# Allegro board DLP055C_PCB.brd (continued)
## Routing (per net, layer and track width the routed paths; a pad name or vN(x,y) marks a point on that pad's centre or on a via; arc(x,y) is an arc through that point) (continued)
HDMI_CEC: length 295.4
  TOP w0.191: v1(118.66,141.92) 118.66,142.57 118.66,142.57 118.66,142.66 118.66,142.66 118.66,143.08 118.66,143.08 J3.23 ; v1(156.41,67.09) 156.13,67.37 156.13,67.76 R234.1 ; J42.49 154.38,8.87 154.38,8.87 154.38,9.29 154.38,9.29 154.38,10.65 156.1,12.37 156.1,14.33 156.1,14.34 TP47.1
  LY12 w0.122: v1(175.74,42.02) 178.18,44.46 179.9,44.46 183.8,48.35 183.8,127.11 181.23,129.68 181.23,144.43 179.12,146.54 161.21,146.54 159,144.33 148.84,144.33 145.39,147.79 134.11,147.79 130.27,143.95 119.45,143.95 118.66,143.16 v1(118.66,141.92)
  BOTTOM w0.191: TP47.1 155.26,16.1 155.26,18.81 154.81,19.26 154.81,40.67 156.74,42.6 169.52,42.6 170.94,41.18 174.9,41.18 v1(175.74,42.02) 175.74,42.38 175.03,43.09 171.6,43.09 170.66,44.03 170.66,46.14 169.74,47.05 167.97,47.05 167.55,47.47 164.65,47.47 162.07,50.05 162.07,50.94 163.02,51.89 163.02,52.25 163,52.28 163,52.98 163.02,53 163.02,55.75 162.81,55.97 162.81,56.59 162.78,56.61 162.78,57.58 162.59,57.77 157.48,57.77 156.53,58.72 149.44,58.72 146.94,61.22 146.94,63.89 147.62,64.58 155.55,64.58 156.41,65.44 v1(156.41,67.09)
HEARTBEAT: length 39.6
  TOP w0.191: U12.2 v1(177.8,88.87) ; U15.AA3 v1(157.45,75.9)
  LY3 w0.076: 158.96,76.49 158.03,76.49 v1(157.45,75.9)
  LY3 w0.102: 158.96,76.49 159.06,76.38 166.91,76.38 166.99,76.3
  LY3 w0.122: 166.99,76.3 174.87,76.3 v1(177.01,78.44)
  LY12 w0.122: v1(177.01,78.44) 177.01,81.51 176.85,81.67 176.85,86.03 177.8,86.98 v1(177.8,88.87)
  BOTTOM w0.191: v1(157.45,75.9) 157.45,72.97 157.68,72.73 157.68,72.42 157.71,72.39 157.71,71.69 157.68,71.67 157.68,71 157.59,70.91 R237.2
HEARTBEAT_DRVR: length 2.6
  TOP w0.191: R32.2 179.71,91.12 179.18,91.65 178.49,91.65 U12.4
HEARTBEAT_LED: length 1.3
  TOP w0.191: R32.1 D15.1
HOLD_BOOTZ: length 19.9
  TOP w0.191: U15.AE4 v1(161.45,76.9)
  LY3 w0.122: v1(170.5,77.29) 166.99,77.29 166.89,77.39 161.94,77.39 v1(161.45,76.9)
  BOTTOM w0.191: v1(170.5,77.29) 170.93,77.72 R119.1 170.93,85.53 170.81,85.65 J9.1
HTPDN: length 75.9
  TOP w0.191: v1(117.67,141) 117.66,141 117.66,142.66 117.66,142.66 117.66,143.08 117.66,143.08 J3.25 ; U15.E17 v1(140.45,90.9)
  LY3 w0.122: v1(140.45,90.9) 139.23,92.11 124.31,92.11 124.14,91.95 v1(121.96,91.95) ; v1(117.67,141) 118.4,141 TP5.1
  LY12 w0.122: TP5.1 121.1,138.29 121.1,132.37 121.41,132.06 121.41,120.68 122.66,119.44 122.66,109.9 122.7,109.85 122.7,109.47 122.66,109.42 122.66,109.33 120.65,107.33 120.65,94.7 121.96,93.39 v1(121.96,91.95)
ICE_RSTZ: length 15.4
  TOP w0.191: U39.2 v1(77.79,11.45)
  LY12 w0.122: v1(77.79,11.45) 77.79,11.96 82.87,17.04 J501.15
  BOTTOM w0.191: R504.1 J501.15
ICTSEN: length 4
  TOP w0.191: U15.K26 v1(145.45,99.9)
  BOTTOM w0.191: R113.2 144.93,102.41 144.93,100.42 v1(145.45,99.9)
IIC0_SCL: length 402.3
  TOP w0.191: v1(33.63,84.87) 33.93,84.57 U561.5 ; J53.1 14.41,107.2 17.47,107.2 17.88,106.79 17.88,104.39 17.58,104.09 U559.5 ; v1(121.15,142.11) 121.16,142.13 121.16,142.66 121.16,142.66 121.16,143.08 121.16,143.08 J3.18 ; U15.E27 v1(140.45,100.9) ; J16.1 v1(110.2,34.87)
  LY3 w0.122: v1(122.47,99.64) 133.42,99.64 134.13,100.35 138.59,100.35 138.7,100.46 140,100.46 v1(140.45,100.9) ; J53.1 14.3,107.32 16.86,107.32 20.57,103.62 20.57,81.77 21.18,81.16 26.31,81.16 27.73,82.58 32.13,82.58 32.51,82.97 32.51,84.46 32.91,84.87 v1(33.63,84.87) ; v1(46.27,145.04) 46.3,145.07 62.62,145.07 63.26,144.43 71.33,144.43 72.22,145.32 77.12,145.32 79.61,142.83 86.18,142.83 90.47,147.13 100.64,147.13 103.57,144.2 120.44,144.2 121.15,143.5 v1(121.15,142.11)
  LY12 w0.122: v1(46.27,145.04) 48.23,143.09 48.23,122.22 46.12,120.12 46.12,96.21 43.77,93.86 41.15,93.86 38.6,91.31 38.6,86.09 38.25,85.73 35.71,85.73 34.84,84.87 v1(33.63,84.87) ; v1(121.15,142.11) 121.59,141.67 121.59,136.85 122.66,135.78 122.66,123.67 121.69,122.7 121.69,121.09 122.94,119.84 122.94,110 122.97,109.97 122.97,109.35 122.94,109.32 122.94,101.66 122.47,101.19 v1(122.47,99.64) 122.47,82.59 123.72,81.34 123.72,73.59 124.46,72.86 124.46,71.31 123.08,69.94 121.33,69.94 119.73,68.33 119.48,68.33 117.37,70.44 110.03,70.44 108.83,69.24 108.83,58.91 104.54,54.62 104.54,46.9 103.3,45.65 103.3,41.67 110.1,34.87 v1(110.2,34.87) 110.2,34.76 117.52,27.44 117.52,18.65 119.99,16.19 119.99,8.95 121.99,6.94 v1(121.99,4.2)
  BOTTOM w0.191: J53.1 16.08,107.31 R585.2 ; v1(121.99,4.2) 121.36,4.2 121.08,3.92 U36.1 ; R147.1 110.2,33.89 v1(110.2,34.87)
IIC0_SDA: length 391.2
  TOP w0.191: U559.4 v1(18.85,99.49) 19.1,99.25 34.97,99.25 35.91,98.31 35.91,94.12 36.39,93.63 v1(36.39,85.18) 37,84.57 U561.4 ; U15.D29 v1(139.45,102.9) ; J3.20 120.16,143.08 120.16,143.08 120.16,142.66 120.16,142.66 v1(120.16,142.19) ; J16.2 v1(111.45,35.26)
  LY3 w0.122: v1(139.45,102.9) 138.93,102.39 138.21,102.39 137.22,103.38 137.14,103.38 136.93,103.59 136.93,104.61 135.23,106.31 130.78,106.31 129.03,108.06 128.45,108.06 126.83,109.68 122.25,109.68 v1(122.23,109.66) ; v1(47.6,144.48) 62.38,144.48 63.01,143.85 71.57,143.85 72.46,144.74 76.88,144.74 79.17,142.45 86.91,142.45 91,146.54 100.4,146.54 103.32,143.62 119.63,143.62 120.16,143.09 v1(120.16,142.19)
  LY12 w0.122: v1(122.23,109.66) 120.16,111.73 120.16,137.7 119.73,138.13 119.73,139.38 120.75,140.4 120.75,141.59 v1(120.16,142.19) ; v1(139.45,102.9) 137.93,101.38 135.53,101.38 131.92,97.77 131.92,91.04 131.29,90.41 129.74,90.41 127.3,87.97 127.3,85.45 131.03,81.72 131.03,75.55 131.9,74.68 131.9,72.2 130.91,71.21 127.78,71.21 127.33,70.75 127.33,68.06 126.54,67.27 119.99,67.27 118.94,68.31 112.62,68.31 110.64,66.33 110.64,58.96 110.31,58.63 110.31,55.48 113.31,52.49 113.31,35.65 112.99,35.33 111.53,35.33 v1(111.45,35.26) 118.23,28.47 118.23,18.83 120.47,16.6 120.47,9.61 v1(121.97,8.11) ; v1(36.39,85.18) 38.6,85.18 39.01,85.58 39.01,91.14 41.32,93.46 43.94,93.46 46.53,96.05 46.53,119.95 48.64,122.06 48.64,143.44 v1(47.6,144.48)
  BOTTOM w0.191: v1(18.85,99.49) 18.85,103.48 17.83,104.5 13.92,104.5 J54.1 9.32,107.31 R599.2 ; v1(111.45,35.26) 111.45,34.76 111.44,34.75 R146.1 ; U36.8 121.08,6.86 121.08,6.86 121.08,7.23 v1(121.97,8.11)
IIC1_SCL: length 277.1
  TOP w0.191: U15.T2 v1(152.45,74.9) ; v1(134.89,23.4) 134.93,23.36 J21.4 ; v1(123.15,142.09) 123.16,142.09 123.16,142.62 123.16,142.63 123.16,143.04 123.16,143.04 J3.14 ; U30.6 v1(106.36,54.27) ; J12.1 v1(110.2,41.84)
  LY3 w0.076: 136.04,74.49 145.7,74.49 145.87,74.31 146.73,74.31 147.08,73.97 147.73,73.97
  LY3 w0.102: v1(152.45,74.9) 152.05,74.5 151.08,74.5 149.92,73.34 ; 148.35,73.34 147.73,73.97 ; 136.04,74.49 135.88,74.32
  LY3 w0.122: 148.35,73.34 148.38,73.31 149.89,73.31 149.92,73.34 ; v1(144.37,54.72) 142.82,54.72 142.66,54.56 142.66,53.18 138.11,48.64 138.11,48.37 137.37,47.62 137.3,47.62 137.15,47.48 115.03,47.48 113.71,48.8 113.71,51.34 111.58,53.48 107.15,53.48 v1(106.36,54.27) ; 135.88,74.32 135.46,73.9 130.96,73.9 v1(130.54,74.32) ; v1(112.66,36.42) 122.55,36.42 124.35,34.62 127.71,34.62 127.93,34.4 133.73,34.4 135.45,32.67 136.7,32.67 141.14,28.23 141.14,27.29 137.89,24.04 135.14,24.04 134.93,23.82 134.93,23.44 v1(134.89,23.4)
  LY12 w0.122: v1(124.86,1.41) 124.86,3.79 129.28,8.21 130.02,8.21 132.53,10.73 132.53,15.33 134.93,17.72 134.93,23.36 v1(134.89,23.4) ; v1(152.45,74.9) 152.95,74.39 152.95,73.39 153.11,73.24 153.11,68.79 154.22,67.67 154.22,65.03 153.16,63.97 152.26,63.97 151.84,63.55 151.84,62.04 150.16,60.36 148.32,60.36 148.32,60.36 148.16,60.36 146.41,58.61 146.41,58.47 146.38,58.44 146.38,58.4 146.38,58.4 146.38,57.62 146.22,57.47 146.22,57.24 146.22,56.02 144.93,54.72 v1(144.37,54.72) ; v1(106.36,54.27) 106.36,53.68 106.39,53.65 106.39,51.27 105.85,50.73 105.85,39.67 109.77,35.76 112.53,35.76 112.66,35.89 v1(112.66,36.42) 112.66,40.84 112.01,41.49 112.01,42.05 111.6,42.45 110.81,42.45 v1(110.2,41.84) ; v1(130.54,74.32) 130.11,74.75 130.11,78.54 123.84,84.81 123.84,141.4 v1(123.15,142.09)
  BOTTOM w0.191: R140.1 110.2,40.87 v1(110.2,41.84) ; v1(124.86,1.41) 124.86,1.81 124.61,2.07 124.33,2.07 124.2,2.19 124.2,2.92 U37.1
IIC1_SDA: length 260.4
  TOP w0.191: U30.5 v1(107.63,54.26) ; U15.T5 v1(152.45,77.9) ; J21.3 v1(133.68,23.42) ; J12.2 v1(111.45,41.84) ; J3.16 122.16,143.04 122.16,143.04 122.16,142.63 122.16,142.62 122.16,142.09 v1(122.16,142.09)
  LY3 w0.076: 135.88,77.51 135.9,77.49 149.98,77.49 150.04,77.43
  LY3 w0.102: 150.04,77.43 150.69,77.43 150.96,77.7 150.96,78.18 151.2,78.42 151.94,78.42 152.45,77.91 v1(152.45,77.9)
  LY3 w0.122: v1(144.83,55.89) 143.15,55.89 142.22,54.96 142.22,53.36 137.85,48.98 137.85,48.48 137.26,47.89 136.75,47.89 136.62,47.76 115.36,47.76 114.14,48.98 114.14,51.52 111.4,54.26 v1(107.63,54.26) ; 135.88,77.51 135.28,77.51 135.21,77.43 134.48,77.43 134.21,77.71 134.21,77.81 133.85,78.17 130.06,78.17 128.32,79.91 v1(126.07,79.91) ; v1(133.68,23.42) 133.68,24.34 134.59,25.26 138.3,25.26 139.34,26.3 139.34,28.38 133.91,33.81 122.16,33.81 120.54,32.19 117.77,32.19 114.22,35.74 112.2,35.74 v1(111.58,36.36)
  LY12 w0.122: v1(152.45,77.9) 152.46,77.9 152.95,77.4 152.95,75.75 152.7,75.5 151.76,75.5 151.02,74.76 151.02,73.19 150.44,72.6 150.44,68.55 151.74,67.26 151.74,66.51 151.69,66.47 151.69,65.61 151.74,65.57 151.74,64.97 150.83,64.06 150.83,62.91 150.52,62.6 150.52,62.57 149.2,61.25 149.17,61.25 148.83,60.92 147.93,60.92 145.85,58.84 145.85,58.7 145.82,58.67 145.82,58.64 145.82,58.63 145.82,57.87 145.54,57.59 145.54,56.6 v1(144.83,55.89) ; 111.45,41.75 110.53,40.83 109.75,40.83 108.43,42.15 108.43,53.46 v1(107.63,54.26) ; 111.45,41.75 111.45,40.19 112.14,39.51 112.14,36.92 v1(111.58,36.36) ; 111.45,41.75 v1(111.45,41.84) ; v1(124.26,11.76) 124.86,11.76 125.98,12.89 125.98,16.09 127.1,17.2 127.46,17.2 v1(133.68,23.42) ; v1(126.07,79.91) 123.25,82.73 123.25,135.94 121.94,137.25 121.94,139.02 122.16,139.24 v1(122.16,142.09)
  BOTTOM w0.191: U37.8 124.26,6.9 124.26,6.9 124.26,7.32 124.26,7.32 v1(124.26,11.76) ; v1(111.45,41.84) 111.45,40.85 R139.1
IIC2_SCL: length 78.3
  TOP w0.191: v1(175.15,45.96) 174.7,45.52 U34.8 173.88,46.35 R79.1 ; J536.1 v1(165.45,37.78) ; J17.7 v1(184.86,38.35)
  LY3 w0.122: v1(175.15,45.96) 174.31,45.12 174.31,40.72 173.15,39.56 167.22,39.56 v1(165.45,37.78)
  BOTTOM w0.191: R124.1 155.64,71.94 155.64,70.94 155.11,70.41 155.11,69.5 157.07,67.54 157.07,65.47 155.93,64.33 155.93,61.54 157.15,60.32 157.15,60.04 157.42,59.77 157.84,59.77 158.42,59.18 162.62,59.18 164.46,57.34 164.46,51.38 164.11,51.02 164.11,49.51 165.01,48.6 171.24,48.6 173.23,46.61 174.5,46.61 v1(175.15,45.96) 176.8,45.96 177.95,44.81 177.95,43.7 181.91,39.73 183.1,39.73 R142.1 184.49,38.35 v1(184.86,38.35) ; R885.1 165.45,36.75 v1(165.45,37.78)
IIC2_SDA: length 76.9
  TOP w0.191: v1(169.71,45.91) 170.1,45.52 U34.1 170.93,46.35 R78.1 170.63,46.69 170.63,47.61 171.1,48.08 176.21,48.08 180.02,44.26 180.02,40.98 v1(183.16,37.85) J17.6 ; J536.2 166.69,36.2 v1(166.69,37.79)
  LY3 w0.122: v1(168.44,71.81) 166.94,73.31 158.13,73.31 v1(156.87,72.04)
  LY12 w0.122: v1(168.44,71.81) 169.85,70.4 169.85,68.72 169.13,68 169.13,51.64 169.71,51.05 v1(169.71,45.91) 169.08,45.28 169.08,44.41 166.7,42.02 166.7,37.8 v1(166.69,37.79)
  BOTTOM w0.191: v1(183.16,37.85) 183.81,37.85 R143.1 ; R127.1 156.53,72.38 v1(156.87,72.04) ; R884.1 v1(166.69,37.79)
IIC_BUSY: length 403.8
  TOP w0.191: TP46.1 8.17,112 12.37,112 13.18,112.81 13.18,114.84 13.86,115.53 15.39,115.53 16.11,114.8 ; 16.11,114.8 v1(16.11,114.78) ; 16.11,114.8 16.46,114.45 U26.34 ; TP6.1 121.66,139.96 J3.17 ; U562.10 21.89,79.35 21.38,79.87 21.38,81.39 22.53,82.53 22.53,84.44 TP146.1 ; J42.51 155.38,10.02 156.73,11.38 v1(158.33,11.38) ; U15.V1 v1(153.95,72.98)
  LY3 w0.122: v1(16.11,114.78) 17.01,113.88 17.22,113.88 18.94,112.15 18.94,108.54 23.26,104.23 23.26,94.19 22.5,93.43 22.5,90.53 23.5,89.53 46.36,89.53 55.24,80.65 101.44,80.65 103.56,82.77 104.91,82.77 105.34,82.34 105.34,81.49 105.94,80.89 108.01,80.89 108.12,80.77 108.12,74.28 109.35,73.05 113.13,73.05 113.18,73 114.78,73 114.83,73.05 114.92,73.05 116.07,74.19 121.24,74.19 122.2,73.24 126.66,73.24 126.8,73.09 v1(130.7,73.09) 130.75,73.05 135.84,73.05 136.04,73.25 137.51,73.25 137.6,73.34 146.04,73.34 146.18,73.2 146.48,73.2 147.77,71.9 148.99,71.9 149.78,72.69 150.05,72.69 150.71,73.35 153.58,73.35 v1(153.95,72.98)
  LY12 w0.122: TP6.1 123.53,138.09 123.53,84.45 129.63,78.36 129.63,74.17 v1(130.7,73.09) ; v1(153.95,72.98) 153.95,70.34 156.91,67.38 156.91,65.91 156.76,65.76 156.76,65.71 156.59,65.54 156.59,65.53 156.57,65.51 156.57,65.5 155.8,64.73 155.79,64.73 153.85,62.79 153.85,62.4 153.19,61.73 153.15,61.73 152.53,61.12 151.71,61.12 150.39,59.8 149.94,59.8 148.39,59.8 146.96,58.37 146.96,58.23 146.94,58.21 146.94,58.17 146.94,58.17 146.94,56.13 146.94,56.13 146.94,56.09 147.13,55.9 147.13,54.96 146.61,54.43 145.64,54.43 144.09,52.88 144.09,52.25 143.58,51.74 143.58,51.64 143.56,51.62 143.56,49.99 143.58,49.97 143.58,49.9 144.71,48.77 148.21,48.77 148.74,48.24 151.94,48.24 155.22,44.97 155.22,34.76 155.72,34.26 155.72,28.72 155.04,28.04 155.04,18.09 158.33,14.8 v1(158.33,11.38) ; TP46.1 4.87,108.7 4.87,92.19 6.22,90.84 20.14,90.84 22.54,88.44 TP146.1
  BOTTOM w0.191: v1(153.95,72.98) 153.96,72.97 R128.1
IIC_SCL_FP: length 25.9
  TOP w0.203: v1(134.88,9.64) 134.88,9.28 134.94,9.21 134.94,8.79 134.88,8.72 J42.10
  LY12 w0.122: v1(134.88,9.64) 134.9,9.62 134.9,9.2 134.9,9.2 134.9,8.81 134.9,8.8 134.9,8.39 127.22,0.72 122.81,0.72 122.47,1.06 v1(122.47,1.73)
  BOTTOM w0.191: U36.4 119.58,2.06 119.58,2.06 119.58,1.65 119.58,1.64 119.58,1.45 119.9,1.13 121.87,1.13 v1(122.47,1.73) 122.76,2.02 U37.4
IIC_SDA_FP: length 22.1
  TOP w0.185: J42.8 v1(133.88,10.38)
  LY3 w0.122: v1(119.23,7.41) 119.3,7.41 119.54,7.65 121.41,7.65 121.74,7.33 v1(122.39,7.33) 123.71,8.64 130.78,8.64 132.51,10.37 133.86,10.37 v1(133.88,10.38)
  BOTTOM w0.191: v1(119.23,7.41) 119.58,7.06 U36.5 ; U37.5 122.77,5.93 122.77,6.95 v1(122.39,7.33)
IR0: length 7.8
  TOP w0.191: U53.1 114.27,81.57 114.27,80.98 112.71,79.43 J88.1
IR0_PWR: length 6.3
  BOTTOM w0.191: C697.2 110.1,88.27 110.55,87.81 111.38,87.81 R257.1 111.44,86.36 U53.3
IR1: length 8.9
  LY12 w0.122: U54.1 106.5,83.32 104.29,83.32 103.82,82.85 J90.1
IR1_PWR: length 6.3
  BOTTOM w0.191: U54.3 103.19,87.74 R258.1 102.55,88.38 C698.2
J9_SP1: length 4.6
  TOP w0.191: TP56.1 87.24,8.97 87.72,8.97 88.15,8.54 J44.1
J9_SP2: length 3.2
  TOP w0.191: J44.2 88.65,9.25 88.65,9.25 88.65,9.66 88.65,9.66 88.65,10.73 TP55.1
J9_SP9: length 3.3
  TOP w0.185: TP54.1 92.15,10.55 J44.9
J9_SP46: length 4.3
  TOP w0.191: TP50.1 111.72,9.8 111.3,9.8 110.65,9.16 110.65,9.07 110.65,9.07 110.65,8.66 110.65,8.65 J44.46
J9_SP49: length 5
  TOP w0.191: TP49.1 114.62,9.83 113.89,9.1 112.5,9.1 112.15,8.76 J44.49
J9_SP50: length 6.4
  TOP w0.191: J44.50 112.65,8.52 112.87,8.74 114.01,8.74 114.64,9.37 115.74,9.37 TP48.1
J10_SP13: length 7.7
  TOP w0.191: TP40.1 81.6,10.82 82.83,12.05 86.03,12.05 J43.13
KEYPD_11: length 5.2
  TOP w0.191: R857.2 9.65,121.28 9.65,120.46 9.37,120.18 J69.11
KEYPD_12: length 6.3
  TOP w0.191: R858.2 9.63,123.2 8.94,123.2 8.68,122.94 8.68,121.24 8.12,120.68 J69.12
KEYPD_13: length 7.4
  TOP w0.191: R152.2 9.62,125.08 8.61,125.08 7.84,124.32 7.84,121.75 7.27,121.18 J69.13
KEYPD_DOWN: length 27.2
  TOP w0.191: J69.4 7.43,116.68 v1(8.54,115.57) R597.1 ; U26.23 v1(20.56,119.95)
  LY3 w0.122: v1(8.54,115.57) 7.17,115.57 5.97,116.77 5.97,120.05 6.35,120.43 13.86,120.43 14.28,120.01 20.51,120.01 v1(20.56,119.95)
KEYPD_LED_HOT: length 15.1
  TOP w0.191: v1(12.4,121.38) 12.3,121.28 R857.1 ; U26.27 v1(20.38,117.96)
  LY3 w0.122: v1(12.4,121.38) 12.97,121.38 13.26,121.67 16.2,121.67 16.85,121.02 20.23,121.02 21.33,119.92 21.33,118.2 21.09,117.96 v1(20.38,117.96)
KEYPD_LED_LMP: length 12.1
  TOP w0.191: R858.1 15.27,123.19 16.63,121.83 16.63,118.37 17.55,117.45 U26.28
KEYPD_LED_PWR: length 19.6
  TOP w0.191: U26.29 v1(20.42,116.95) ; R152.1 v1(12.33,125.09)
  LY3 w0.122: v1(20.42,116.95) 21.72,116.95 22.02,117.26 22.02,120.02 21.36,120.68 21.36,122.13 20.82,122.67 14.76,122.67 v1(12.33,125.09)
KEYPD_LEFT: length 19.6
  TOP w0.191: R610.1 v1(8.49,116.84) 8.15,117.18 J69.5 ; U26.24 v1(17.45,119.46)
  LY3 w0.122: v1(17.45,119.46) 14.36,119.46 13.79,120.02 7.74,120.02 7.41,119.69 7.41,117.38 7.96,116.84 v1(8.49,116.84)
KEYPD_P3P3V: length 7.9
  TOP w0.191: J69.1 3.98,115.18 3.43,115.73 3.43,118.25 v1(3.92,118.75) 3.99,118.68 J69.8
  BOTTOM w0.191: R612.2 v1(3.92,118.75)
KEYPD_PWR: length 16.6
  TOP w0.191: U26.26 v1(17.48,118.46) ; J69.7 6.26,118.18 6.47,117.97 6.51,117.97 6.52,117.96 6.92,117.96 6.92,117.97 7.44,117.97 7.79,118.32 7.79,119.13 v1(8.04,119.38) R611.1
  LY3 w0.122: v1(8.04,119.38) 9.66,119.38 10.31,118.73 13.28,118.73 13.79,118.22 17.24,118.22 v1(17.48,118.46)
KEYPD_RIGHT: length 19
  TOP w0.191: R598.1 v1(8.45,118.11) 7.98,117.64 7.6,117.64 7.58,117.63 7.06,117.63 7.06,117.62 6.38,117.62 6.37,117.63 6.33,117.63 6.28,117.68 J69.6 ; U26.25 v1(20.72,118.96)
  LY3 w0.122: v1(8.45,118.11) 9.02,118.11 9.6,117.53 17.88,117.53 19.25,118.91 20.67,118.91 v1(20.72,118.96)
KEYPD_SEL: length 29.9
  TOP w0.191: v1(17.32,121.55) 17.91,120.95 U26.21 ; R596.1 v1(7.9,113.03) 7.13,113.8 7.13,114.92 6.37,115.68 J69.2
  LY3 w0.122: v1(7.9,113.03) 6.46,113.03 5.28,114.21 5.28,120.58 5.84,121.14 10.97,121.14 11.83,122.01 16.86,122.01 v1(17.32,121.55)
KEYPD_UP: length 26.5
  TOP w0.191: U26.22 17.57,120.45 v1(17.53,120.49) ; J69.3 6.69,116.18 v1(8.11,114.75) 8.56,114.3 R609.1
  LY3 w0.122: v1(8.11,114.75) 6.28,114.75 5.63,115.4 5.63,120.53 5.98,120.87 11.08,120.87 11.09,120.89 13.51,120.89 13.78,121.16 16.04,121.16 16.7,120.49 v1(17.53,120.49)
LAMPLITZ: length 11.3
  TOP w0.191: J27.1 177.36,17.83 176.78,18.41 J26.1
  BOTTOM w0.191: J26.1 174.83,18.53 R55.2 R529.2
LAMPLITZ_FLTR: length 11
  BOTTOM w0.191: TP263.1 166.95,18.15 166.95,19.31 167.32,19.68 U11.2 168.71,19.72 169.62,19.72 169.97,20.07 169.97,20.58 170.78,21.39 C10.2 R55.1
LD_SPOKE_OFFZ: length 10.8
  TOP w0.191: U49.8 v1(112.37,72.54)
  BOTTOM w0.191: v1(112.37,72.54) 110.7,72.54 109.14,74.1 107.87,74.1 R667.1 TP167.1
LD_SPOKE_OFFZ_OUT: length 33.1
  TOP w0.191: J115.2 v1(105.18,56.54) ; v1(109.39,62.14) 110.1,62.84 110.11,62.84 110.59,63.32 110.59,63.33 111.17,63.92 111.66,63.92 111.67,63.92 112.02,63.92 112.08,63.98 112.3,63.98 112.37,64.05 U49.17
  LY3 w0.122: J97.18 120.81,50.89 119.81,51.9 115.59,51.9 111.88,55.61 106.12,55.61 v1(105.18,56.54)
  BOTTOM w0.191: v1(105.18,56.54) 105.18,58.13 105.69,58.63 108.02,58.63 108.73,59.34 108.73,61.48 v1(109.39,62.14)
LED_EN: length 8.9
  TOP w0.191: J106.2 101.75,61.22 103.24,61.22 105.02,59.44 106.29,59.44 106.43,59.3 J115.3
LED_EN_BLU: length 34.1
  TOP w0.191: J115.8 v1(112.68,56.71) ; v1(115.13,66.3) 114.97,66.14 U49.21
  LY3 w0.122: v1(112.68,56.71) 117.23,52.17 129.47,52.17 130.75,50.89 J97.8
  LY12 w0.122: v1(115.13,66.3) 115.13,59.17 v1(112.68,56.71)
LED_EN_GRN: length 37.8
  TOP w0.191: v1(111.38,56.42) 111.43,56.48 J115.7 111.4,58.24 111.4,59.95 110.59,60.77 110.59,61.79 111.02,62.22 111.02,62.3 111.96,63.24 112.31,63.24 112.36,63.29 113.14,63.29 113.46,63.61 115.24,63.61 115.62,64 U49.22
  LY3 w0.122: J97.6 132.84,52.05 132.41,52.49 117.85,52.49 113.13,57.21 112.16,57.21 v1(111.38,56.42)
LED_EN_IR: length 20.5
  TOP w0.191: U49.20 114.32,66.17 v1(114.17,66.33)
  LY12 w0.122: v1(114.17,66.33) 114.14,66.33 111.1,63.28 111.1,57.89 112.09,56.9 112.09,55.65 J97.22
LED_EN_RED: length 41.5
  TOP w0.191: v1(116.53,63.53) 116.27,63.79 U49.23 ; J115.6 110.18,59.69 v1(110.11,59.76)
  LY3 w0.122: J97.4 134.84,52.13 134.13,52.84 118.51,52.84 113.13,58.23 111.76,58.23 110.22,59.76 v1(110.11,59.76) 110.18,59.83 110.18,61.96 111.68,63.46 116.46,63.46 v1(116.53,63.53)
LED_EN_UV: length 25
  TOP w0.191: U49.19 113.67,66.09 113.48,66.28 v1(112.82,66.28)
  LY12 w0.122: J97.20 117.8,51.94 117.8,59.09 119.1,60.38 119.1,65.21 116.86,67.45 114.42,67.45 113.25,66.28 v1(112.82,66.28)
LEDSEL_0: length 53.5
  TOP w0.191: U15.AB3 v1(158.45,75.9) ; v1(116.97,72.33) 116.46,72.33 116.27,72.14 U49.2 116.27,69.97 116.35,69.88 116.35,69.63 v1(116.28,69.55)
  LY3 w0.122: v1(116.97,72.33) 118.27,72.33 118.64,72.7 126.44,72.7 126.82,72.32 137.33,72.32 137.82,72.81 144.85,72.81 144.98,72.68 145.83,72.68 147.29,71.22 149.21,71.22 150.14,72.14 150.36,72.14 151.03,72.81 151.31,72.81 151.32,72.83 151.71,72.83 151.72,72.81 152.37,72.81 152.39,72.84 152.78,72.84 152.8,72.81 152.84,72.81 153.46,72.2 155.83,72.2 158.01,74.38 158.59,74.38 158.95,74.74 158.95,75.29 158.45,75.8 v1(158.45,75.9)
  BOTTOM w0.191: v1(116.28,69.55) 116.35,69.63 118.13,69.63 118.44,69.33 118.44,68.79 R666.1
LEDSEL_1: length 50.5
  TOP w0.191: v1(115.49,69.5) 115.62,69.64 U49.3 v1(115.62,72.57) ; U15.AB2 v1(158.45,74.9)
  LY3 w0.122: v1(158.45,74.9) 158,74.9 155.6,72.51 153.53,72.51 152.95,73.08 152.91,73.08 152.89,73.1 152.28,73.1 152.27,73.08 151.83,73.08 151.82,73.09 151.6,73.09 151.21,73.09 151.2,73.08 150.82,73.08 150.15,72.41 150.03,72.41 149.14,71.52 147.74,71.52 146.42,72.84 146.1,72.84 145.87,73.07 137.71,73.07 137.58,72.95 137.07,72.95 136.72,72.6 126.92,72.6 126.55,72.97 116.02,72.97 v1(115.62,72.57)
  BOTTOM w0.191: v1(115.49,69.5) 115.57,69.42 R665.1
LEDSEL_2: length 61.2
  TOP w0.191: v1(114.73,69.48) 114.97,69.72 U49.4 ; U15.AA5 v1(157.45,77.9)
  LY3 w0.122: v1(159.51,71.36) 159.51,70.67 159.35,70.51 153.7,70.51 152.89,71.32 151.11,71.32 150.84,71.05 150.67,71.05 148.97,69.35 144.23,69.35 144.22,69.34 139.52,69.34 138.21,70.65 135.72,70.65 134.98,71.39 128.39,71.39 128.16,71.17 124.45,71.17 123.39,70.11 123.14,70.11 J530.2 120.58,69.6 118.67,69.6 117.63,68.57 116.45,68.57 116.02,69 115.2,69 v1(114.73,69.48)
  BOTTOM w0.191: R664.1 114.62,68.99 114.73,69.1 v1(114.73,69.48) ; v1(159.51,71.36) 158.53,72.33 158.53,73.04 158.97,73.47 158.97,77.21 158.78,77.4 157.94,77.4 v1(157.45,77.9)
LEDSEL_3: length 56.6
  TOP w0.191: v1(113.94,69.48) 114.32,69.86 U49.5 ; U15.AA4 v1(157.45,76.9)
  LY3 w0.122: v1(158.7,71.08) 155.24,71.08 154.86,71.46 153.13,71.46 153,71.59 151,71.59 150.74,71.33 150.14,71.33 149.16,70.35 142.26,70.35 141.22,71.39 138.52,71.39 138.17,71.74 128.36,71.74 128.06,71.43 124.34,71.43 124.06,71.15 123.67,71.15 122.47,69.96 117.17,69.96 117.07,70.06 114.52,70.06 v1(113.94,69.48)
  BOTTOM w0.191: v1(158.7,71.08) 158.05,71.73 158.05,72.54 158.04,72.55 158.04,72.85 158.03,72.86 158.03,72.88 157.93,72.97 157.93,76.41 v1(157.45,76.9) ; v1(113.94,69.48) 113.94,69.38 R663.1
LEDSEL_4: length 58.8
  TOP w0.191: U49.6 113.67,69.92 113.38,69.63 v1(112.04,69.63)
  LY3 w0.122: v1(112.04,69.63) 113,70.6 118.18,70.6 119.92,72.34 122.67,72.34 123.41,71.59 124.11,71.59 124.23,71.7 127.82,71.7 128.14,72.02 138.65,72.02 138.98,71.69 141.3,71.69 142.33,70.66 143.75,70.66 144.47,71.37 146.32,71.37 146.94,70.76 149.12,70.76 150.04,71.67 150.47,71.67 150.69,71.89 153.5,71.89 153.61,71.79 155.77,71.79 156.07,71.48 157.04,71.48 157.41,71.85 159.69,71.85 159.7,71.85 159.87,71.85 160.19,71.53 160.19,71.1 v1(160.68,70.62)
  BOTTOM w0.191: R237.1 159.36,69.99 159.99,70.62 v1(160.68,70.62) ; v1(112.04,69.63) 112.04,68.83 R662.1
LL_FAULT: length 27.7
  TOP w0.191: U16.2 TP24.1 ; U15.AB4 v1(158.45,76.9)
  LY3 w0.076: 160.64,77.31 160.28,77.31 160.27,77.31 159.62,77.31 159.62,77.31 159.28,77.31 159.27,77.31 158.95,77.31 158.54,76.9
  LY3 w0.102: v1(158.45,76.9) 158.54,76.9 ; 160.64,77.31 160.96,77.63 160.96,78.22 161.13,78.39 165.17,78.39 165.73,77.83 166.99,77.83
  LY3 w0.122: TP24.1 177.01,82.08 177.01,79.21 175.64,77.83 166.99,77.83
LL_FAULT_DRVR: length 3.2
  TOP w0.191: R40.2 178.69,88.27 178.45,88.02 U16.4
LL_FAULT_LED: length 1.3
  TOP w0.191: R40.1 D6.1
LMP_HOT: length 6.7
  BOTTOM w0.191: J530.1 123.51,73.03 R511.1 124.89,75.45 J11.1
LMP_TXD: length 48.5
  TOP w0.191: R524.2 R526.1 174.94,28.9 v1(174.44,29.4)
  LY12 w0.122: v1(172.47,69.22) 174.29,67.4 174.29,54.62 172.39,52.71 172.39,46.21 171.2,45.02 171.2,39.45 173.91,36.74 173.91,33.18 174.44,32.65 v1(174.44,29.4)
  BOTTOM w0.191: R710.1 v1(172.47,69.22) ; U9.2 174.44,28.16 v1(174.44,29.4)
LMP_TXD_BUF: length 3
  TOP w0.191: J27.5 182.16,22.86 v1(184.1,22.86)
  BOTTOM w0.191: R56.2 v1(184.1,22.86)
LMP_TXD_BUF_OUT: length 7.8
  LY3 w0.122: v1(180.59,22.86) 178.13,25.32 v1(176.31,25.32)
  BOTTOM w0.191: R56.1 v1(180.59,22.86) ; U9.4 v1(176.31,25.32)
LMP_TXD_BUF_PWR: length 4.2
  TOP w0.191: 172.42,25.92 R52.2 ; 172.42,25.92 173.02,26.53 v1(173.12,26.53) ; 172.42,25.92 C504.2
  BOTTOM w0.191: v1(173.12,26.53) 173.12,25.55 U9.5
LMPCTRL: length 149.3
  TOP w0.191: TP219.1 148.39,63.39 R712.1 ; v1(111.03,69.42) 111.07,69.46 U49.10 ; R525.2 180.14,27.97 v1(179.45,28.66) ; U15.W4 v1(155.45,76.9)
  LY3 w0.122: v1(111.03,69.42) 111.03,68.34 111.53,67.84 116.48,67.84 117.22,67.1 117.22,66.79 120.37,63.64 124.18,63.64 127.75,67.21 133.63,67.21 134.49,66.35 134.49,65.23 136.08,63.64 146.17,63.64 146.3,63.5 TP219.1
  LY12 w0.122: v1(179.45,28.66) 179.52,28.58 179.52,19.9 180.08,19.34 v1(180.08,17.28) ; v1(155.45,76.9) 155.44,76.9 154.96,77.38 154.96,78.22 154.78,78.39 149.22,78.39 148.97,78.14 148.97,77.61 148.76,77.4 147.19,77.4 146.96,77.17 146.96,71.36 147.09,71.23 147.09,68.46 146.99,68.36 146.99,64.79 TP219.1
  BOTTOM w0.191: R660.1 111.03,69.32 v1(111.03,69.42) ; TP219.1 150.83,63.5 151.63,62.7 151.63,61.43 153.31,59.75 155.99,59.75 157.31,58.43 162.7,58.43 163.88,57.25 163.88,55.44 163.37,54.92 163.37,52.86 163.34,52.84 163.34,52.42 163.37,52.4 163.37,51.85 163.67,51.55 163.67,49.45 165.16,47.96 170.28,47.96 171.67,46.57 172.31,46.57 172.92,45.96 174.04,45.96 174.65,45.35 176.09,45.35 176.4,45.04 176.4,35.44 176.78,35.06 176.78,31.02 TP264.1 178.94,30.08 179.45,29.57 v1(179.45,28.66) 179.45,27.44 U567.2 ; R54.2 179.74,16.94 v1(180.08,17.28)
LMPCTRL_B: length 19.4
  TOP w0.191: J106.3 102.11,65.98 104.01,67.88 107.64,67.88 109.09,66.43 110.79,66.43 111.07,66.15 U49.15
  BOTTOM w0.191: U48.2 101.59,66.04 101.34,65.79 101.34,63.63 J106.3
LMPCTRL_BUF: length 2.1
  BOTTOM w0.191: R53.1 182.03,24.11 180.67,24.11 180.34,24.44 U567.4
LMPCTRL_BUF_PWR: length 4.2
  TOP w0.191: C503.2 R51.2 178.12,23.9 178.31,23.71 v1(178.41,23.71)
  BOTTOM w0.191: U567.5 178.41,24.65 v1(178.41,23.71)
LMPCTRL_BUF_R: length 3.2
  TOP w0.191: v1(184.19,24.13) 182.18,24.13 J27.6
  BOTTOM w0.191: R53.2 v1(184.19,24.13)
LMPCTRL_BZ: length 5.6
  BOTTOM w0.191: J106.1 97.36,63.61 R860.1 98.44,65.41 98.75,65.09 U48.4
LMPCTRL_R: length 2.4
  BOTTOM w0.191: R54.1 178.71,18.66 178.71,19.85 177.91,20.65 Q1.1
LMPCTRL_Z: length 7.4
  BOTTOM w0.191: J26.2 174.95,20.96 176.45,20.96 177.08,21.59 Q1.3 R57.1
LMPCTRL_Z_R: length 3
  TOP w0.191: v1(184.09,21.59) 182.14,21.59 J27.4
  BOTTOM w0.191: R57.2 v1(184.09,21.59)
LMPSTAT: length 102.7
  TOP w0.191: TP220.1 152.72,63.77 151.26,65.23 151.26,66.82 152.28,67.84 153.94,67.84 153.95,67.85 154,67.85 154.63,68.49 154.63,70.27 155.16,70.8 155.16,72.98 154.45,73.7 v1(154.45,74.9) ; U15.W3 v1(155.45,75.9)
  LY12 w0.122: v1(154.45,74.9) 154.45,73.45 154.94,72.96 154.94,72.51 155.18,72.27 155.18,69.5 157.2,67.48 157.2,65.8 157.04,65.65 157.04,65.59 156.87,65.42 156.87,65.42 156.84,65.39 156.84,65.38 155.92,64.45 155.91,64.45 154.13,62.67 154.13,62.28 153.3,61.46 153.27,61.46 152.55,60.74 151.86,60.74 150.64,59.52 149.83,59.52 148.51,59.52 147.24,58.26 147.24,58.12 147.22,58.09 147.22,58.06 147.21,58.05 147.21,56.25 147.22,56.24 147.22,56.21 147.41,56.01 147.41,54.8 146.72,54.1 145.7,54.1 144.37,52.77 144.37,52.13 143.86,51.62 143.86,51.52 143.84,51.5 143.84,50.1 143.86,50.08 143.86,50.02 144.82,49.05 148.44,49.05 148.95,48.54 152.03,48.54 155.49,45.08 155.49,34.88 156.05,34.32 156.05,28.58 155.32,27.85 155.32,21.12 v1(155.79,20.64)
  BOTTOM w0.191: U11.4 157.7,18.74 v1(155.79,20.64) ; v1(154.45,74.9) 155.45,75.9 v1(155.45,75.9)
  BOTTOM w0.305: v1(154.45,74.9) 153.84,74.9 153.76,74.98 R713.1
LMPSYNC: length 57.6
  TOP w0.191: U15.V5 v1(154.45,77.9) ; U49.9 111.72,73.06 TP218.1
  LY3 w0.076: 135.91,75.04 136.18,75.31 136.2,75.31 136.55,75.31 136.69,75.31 137.2,75.31 138.2,75.31 138.35,75.31 138.69,75.31 139.2,75.31 139.35,75.31 139.69,75.31 140.2,75.31 141.2,75.31 141.35,75.31 141.69,75.31 142.2,75.31 142.35,75.31 142.69,75.31 143.2,75.31 143.35,75.31 143.69,75.31 144.2,75.31 145.2,75.31 145.25,75.31 146.08,74.49 147.25,74.49 147.27,74.51 ; 154.03,77.48 153.69,77.48 153.69,77.49 153.35,77.49 153.35,77.49 153.21,77.49 153.2,77.48 152.69,77.48 152.69,77.49 152.35,77.49 152.35,77.49 152.21,77.49 152.2,77.48 151.69,77.48 151.69,77.49 151.2,77.49 151.12,77.48 150.86,77.23 150.86,77.14 150.86,77.14 150.86,77.12 150.86,77.12 150.86,76.97 150.86,76.58 150.86,76.58 150.86,76.39 150.96,76.3 150.96,75.52 150.85,75.41 150.85,74.95
  LY3 w0.102: 150.85,74.95 150.33,74.43 148.03,74.43 147.95,74.51 147.27,74.51 ; v1(154.45,77.9) 154.03,77.48
  LY3 w0.122: 135.91,75.04 135.88,75.04 135.05,74.22 131.4,74.22 130.68,74.94 130.46,74.94 128.55,76.84 122.04,76.84 120.44,75.24 116.71,75.24 114.78,73.32 114.72,73.32 114.67,73.27 113.29,73.27 113.24,73.32 111.47,73.32 TP218.1
  BOTTOM w0.191: R261.1 152.95,76.35 152.95,77.2 153.16,77.4 153.95,77.4 v1(154.45,77.9)
LOCKN: length 79.1
  TOP w0.191: J3.26 117.16,141.94 v1(116.83,141.6) ; R9.1 118.49,134.62 D1.1 TP3.1 ; U15.E19 v1(140.45,92.9)
  LY3 w0.122: v1(120.61,93.35) 121.45,92.51 135.88,92.51 135.96,92.43 139.97,92.43 v1(140.45,92.9)
  LY12 w0.122: v1(120.61,93.35) 118.43,95.53 TP3.1 116.83,140.35 v1(116.83,141.6)
LOCKN_LED: length 1.4
  TOP w0.191: R10.1 118.58,133.03 D1.2
LVDS_VREFTEST: length 15.2
  TOP w0.191: U15.AF16 162.46,88.88 167.94,88.88 169.46,87.36 169.46,86.09 169.91,85.64 173.06,85.64 173.13,85.58 173.18,85.58 TP159.1
MSP_IIC0_SCL: length 16.8
  TOP w0.191: J53.2 15.32,109.86 16.05,109.13 18.94,109.13 20.32,110.5 20.32,111.51 20.87,112.07 23.24,112.07 23.97,111.34 U26.47
  BOTTOM w0.191: J53.2 16.08,109.86 R585.1
MSP_IIC0_SDA: length 17.8
  TOP w0.191: U26.46 23.47,110.65 v1(22.81,111.31)
  BOTTOM w0.191: v1(22.81,111.31) 22.81,111.34 22.14,112 13.25,112 J54.2 9.32,109.86 R599.1
MSP_LED2: length 24.4
  TOP w0.191: v1(10.36,130.08) 8.47,130.08 D52.1
  BOTTOM w0.191: R856.2 21.39,119.84 19.48,121.75 19.48,123.02 17.14,125.36 17.14,128.99 16.05,130.08 v1(10.36,130.08)
MSP_LED2_DRVR: length 2.1
  BOTTOM w0.191: U558.4 22.65,115.79 R856.1
MSP_LED2_ONZ: length 8.9
  TOP w0.191: U26.56 v1(28.47,111.41)
  BOTTOM w0.191: v1(28.47,111.41) 28.11,111.77 28.11,116.16 27.83,116.44 U558.2
MSP_PROJ_ON: length 60.7
  TOP w0.191: U565.2 R865.1 v1(60.93,142.76)
  LY3 w0.122: v1(60.93,142.76) 60.29,142.76 59.2,143.85 42.34,143.85 35.07,136.58 35.07,132.37 24.12,121.41 v1(24.12,113.67)
  BOTTOM w0.191: R608.1 v1(24.12,113.67)
MSP_RSTNMI: length 30.1
  TOP w0.191: U26.76 33.47,118.96 38.74,113.69 41.27,113.69 41.28,113.67 42.6,114.99 45.56,114.99 46.25,114.31 49.84,114.31 J70.11
  BOTTOM w0.191: J70.11 49.81,114.33 46.94,114.33 45.87,113.27 R592.2
MSP_V18: length 3.3
  TOP w0.191: U26.67 31.1,114.45 v1(30.76,114.11)
  BOTTOM w0.191: v1(30.76,114.11) 31.76,114.11 C531.2
MSP_VCORE: length 3.4
  TOP w0.191: v1(20.04,124.16) 20.75,124.16 20.97,123.94 U26.20
  BOTTOM w0.191: C521.1 20.64,123.56 v1(20.04,124.16)
MSPIF_VCC1: length 5.1
  TOP w0.191: R606.2 v1(45,102.47)
  LY3 w0.122: v1(45,102.47) 45.4,102.87 J70.4
MSPIF_VCC2: length 5.1
  TOP w0.191: J70.2 44.61,100.33 44.37,100.57 R607.2
MSPJTAG_TCK: length 24.3
  TOP w0.191: U26.75 33.47,118.46 38.58,113.34 41.13,113.34 41.41,113.06 41.42,113.06 42.45,112.04 46.57,112.04 46.94,111.67 49.55,111.67 49.93,111.29 49.93,109.13 J70.7
MSPJTAG_TDI: length 27.2
  TOP w0.191: U26.73 33.42,117.45 38.4,112.48 40.69,112.48 42.87,110.3 45.92,110.3 47.19,109.03 47.19,104.78 47.9,104.07 49.91,104.07 J70.3
MSPJTAG_TDO: length 29.2
  TOP w0.191: U26.72 33.44,116.95 38.32,112.07 40.33,112.07 41.93,110.47 41.95,110.47 42.47,109.95 42.49,109.95 42.58,109.86 45.21,109.86 45.94,109.13 45.94,102.88 47.24,101.58 49.86,101.58 J70.1
MSPJTAG_TMS: length 25.1
  TOP w0.191: U26.74 33.41,117.96 38.5,112.86 40.97,112.86 42.67,111.16 46.12,111.16 48.05,109.23 49.32,109.23 49.74,108.81 49.74,106.79 J70.5
MTR_ARSTZ: length 202.9
  TOP w0.191: TP240.1 62.58,64.8 64.61,64.8 64.88,64.54 U555.48 ; U15.AF27 v1(162.45,100.9)
  LY3 w0.076: 142.91,97.49 141.62,97.49 141.62,97.49 141.28,97.49 141.27,97.49 140.62,97.49 140.62,97.49 140.28,97.49 140.27,97.49 139.87,97.49 139.71,97.65 137.82,97.65 137.56,97.39 135.93,97.39 135.88,97.44
  LY3 w0.102: 142.91,97.49 143.37,97.96 158.34,97.96 158.96,98.57 158.96,99.13 159.2,99.37 159.58,99.37 159.94,99.73 159.94,100.28 160.1,100.44 162.02,100.44 162.45,100.87 v1(162.45,100.9)
  LY3 w0.122: TP240.1 61.29,66.02 49.68,66.02 44.65,60.99 28.42,60.99 25.9,58.48 23.69,58.48 v1(22.85,57.63) ; v1(71.88,110.68) 74.04,108.52 84.35,108.52 87.63,105.24 87.93,105.24 90.27,102.9 93.14,102.9 97.43,98.61 119.79,98.61 120.34,98.06 135.27,98.06 135.88,97.44
  LY12 w0.122: TP240.1 71.29,73.52 71.29,95.23 73.1,97.04 73.1,105.24 72.46,105.88 72.46,110.09 v1(71.88,110.68)
  BOTTOM w0.191: R790.1 22.97,56.01 22.85,56.13 v1(22.85,57.63) ; R766.1 TP240.1 ; R811.1 72.5,110.06 v1(71.88,110.68)
Net_605: length 0.7
  TOP w0.191: 151.95,99.4 v1(152.45,99.9)
Net_606: length 0.7
  TOP w0.191: 150.95,103.4 v1(150.45,103.9)
Net_607: length 0.7
  TOP w0.191: 151.95,102.4 v1(152.45,102.9)
NFAULT: length 1.3
  TOP w0.191: R73.2 151.33,46.52 151.17,46.35 U35.8
NSLEEP: length 1.3
  TOP w0.191: U35.1 151.17,40.74 151.33,40.58 R81.1
OCLKA: length 279.1
  TOP w0.191: R635.2 155.64,108.47 154.4,109.71 v1(152.55,109.71) ; TP236.1 60.64,59.97 61.02,59.59 61.76,59.59 61.85,59.5 61.87,59.5 62.07,59.31 U555.6
  LY3 w0.122: v1(81.61,104.66) 79.8,104.66 79.35,105.11 79.35,106.82 78.41,107.76 74.6,107.76 73.91,107.07 73.91,104.05 72.51,102.65 72.51,100.24 71.01,98.74 68.19,98.74 v1(65.52,101.41) ; TP236.1 59.18,59.5 51.26,59.5 48.56,56.8 45.49,56.8 44.6,55.91 43.63,55.91 43.02,56.52 38.35,56.52 37.05,55.23 37.05,48.4 36.17,47.51 25.62,47.51 24.3,48.83 24.3,53.37 21.79,55.89 16.63,55.89 v1(16.62,55.88)
  LY12 w0.122: TP236.1 55.63,60.96 54.15,62.44 54.15,66.4 64.79,77.05 64.79,100.68 v1(65.52,101.41)
  BOTTOM w0.191: R784.2 v1(16.62,55.88) ; R805.2 v1(65.52,101.41) ; v1(81.61,104.66) 82.42,105.47 85.24,105.47 85.95,106.18 85.95,111.69 87.8,113.55 87.8,120.02 86.43,121.4 85.14,121.4 84.96,121.57 84.96,131.42 85.24,131.7 85.24,135.06 85.64,135.46 91.71,135.46 94.71,138.46 101.8,138.46 106.02,134.25 118.21,134.25 118.56,133.89 132.89,133.89 137.64,129.14 149.93,129.14 153.74,125.33 153.74,113.04 153.76,113.03 153.76,111.78 153.74,111.77 153.74,110.91 v1(152.55,109.71)
OCLKA_T: length 4.4
  TOP w0.191: R635.1 159.08,107.42 159.08,104.89 159.95,104.01 U15.AD30
OSC_38MHZ: length 3
  BOTTOM w0.191: R589.1 R604.1 132.19,92.71 U500.3
OSC_40MHZ: length 2
  BOTTOM w0.191: U502.3 179.3,91.91 U503.1
OUT0A: length 8.3
  TOP w0.191: DN1.3 54.8,39.64 54.5,39.94 v1(53.62,39.94) 52.66,38.99 J515.4
  BOTTOM w0.191: R768.1 R775.1 53.62,38.87 v1(53.62,39.94)
OUT0B: length 8.6
  TOP w0.191: DN3.3 44.01,38.91 v1(45.34,40.24) 45.59,39.99 J515.3
  BOTTOM w0.191: R774.1 44.01,38.91 v1(45.34,40.24) 44.05,40.24 R769.1
OUT0C: length 12.4
  TOP w0.191: DN2.3 57.9,38.9 55.83,40.98 52.67,40.98 v1(52.61,40.92) 50.93,40.92 J515.2
  BOTTOM w0.191: v1(52.61,40.92) R771.1 50.58,41.33 R773.1
OUT1A: length 18
  TOP w0.191: DN5.3 28.26,34.23 26.84,35.65 26.84,38.42 v1(26.78,38.48) 27.63,38.48 28.24,37.87 J519.4
  LY3 w0.122: v1(23.19,43.29) 23.19,41.88 24.54,40.53 24.74,40.53 v1(26.78,38.48)
  BOTTOM w0.191: v1(23.19,43.29) 23.19,43.72 23.71,44.25 R785.1 ; R796.1 v1(26.78,38.48)
OUT1B: length 12.6
  TOP w0.191: DN7.3 25.08,34.59 23.67,36 v1(23.67,39.46) 24.2,39.46 24.79,38.87 J519.3
  BOTTOM w0.191: R795.1 24.46,38.13 24.46,38.59 23.67,39.38 v1(23.67,39.46) 24.02,39.8 R787.1
OUT1C: length 16.5
  TOP w0.191: v1(27.16,40.44) 27.68,40.44 28.24,39.87 J519.2 29.29,39.87 29.94,40.52 30.35,40.52 31.43,39.44 DN6.3
  BOTTOM w0.191: v1(27.16,40.44) R792.1 28.96,40.37 30.37,40.37 31.23,41.22 R794.1
OUT2A: length 15
  TOP w0.191: J523.4 77.71,86.76 77.26,87.21 v1(77.26,89.16)
  LY3 w0.122: v1(77.26,89.16) 76.57,89.85 v1(72.66,89.85)
  BOTTOM w0.191: v1(77.26,89.16) 79,89.16 R817.1 ; R806.1 DN9.3 v1(72.66,89.85)
OUT2B: length 25.5
  TOP w0.191: DN11.3 v1(70.07,93.03) ; v1(77.01,91.24) 77.01,90.66 76.65,90.31 76.65,87.94 76.47,87.76 J523.3
  LY3 w0.122: v1(77.01,91.24) 76.31,91.24 75.87,91.68 71.42,91.68 v1(70.07,93.03)
  LY12 w0.122: v1(77.01,91.24) 74.98,89.2 74.98,87.49 v1(72.15,84.66)
  BOTTOM w0.191: R808.1 v1(77.01,91.24) ; R816.1 v1(72.15,84.66)
OUT2C: length 20.9
  TOP w0.191: v1(78.93,90.13) J523.2
  LY3 w0.122: v1(78.93,90.13) 78.65,90.41 71.9,90.41 71.35,89.85 v1(70.21,89.85)
  BOTTOM w0.191: v1(78.93,90.13) 79.06,90.26 R813.1 79.07,91.22 80.03,91.22 80.53,90.72 R815.1 ; DN10.3 v1(70.21,89.85)
P1P8_DRAIN_EN: length 5.7
  TOP w0.191: v1(85.59,92.38) 86.91,92.38 U526.8
  BOTTOM w0.191: U523.1 v1(85.59,92.38) 86.55,93.34 R195.1
P1P8V: length 57
  TOP w0.254: v1(172.1,44.52) U34.3
  TOP w0.381: C760.1 91.7,47.57 v1(92.81,47.57) ; U15.L16 v1(146.45,89.9) ; U15.AE14 v1(161.45,86.9) ; v1(139.87,70.88) 139.22,70.88 138.83,70.5 138.83,69.85 ; 138.83,69.85 138.83,69.18 139.22,68.8 v1(139.87,68.8) ; 138.83,69.85 C95.1 ; 138.83,69.85 v1(139.87,69.85) ; U15.AE13 v1(161.45,85.9) ; 132.72,81.05 132.09,81.05 131.71,81.43 v1(131.71,82.08) ; 132.72,81.05 v1(132.72,82.08) ; 132.72,81.05 C74.1 ; 132.72,81.05 133.39,81.05 133.69,81.36 v1(133.69,82.08) ; R83.1 173.15,42.04 v1(173.14,42.02) ; U15.T25 v1(152.45,98.9) ; R82.1 171.65,42.06 v1(171.74,41.98) ; U15.Y15 v1(156.45,87.9) ; U15.R6 v1(150.45,78.9) ; U15.AE16 v1(161.45,89.9)
  TOP w0.635: TP227.1 91.9,43.95 ; TP227.1 90.82,42.88 ; TP227.1 90.82,43.95 ; TP227.1 91.9,42.88 ; C761.1 90.94,52.48 90.51,52.91 v1(88.88,52.91)
  BOTTOM w0.305: C241.1 v1(157.47,81.83) ; C240.2 v1(157.29,86.24) ; v1(142.53,92.94) 142.58,92.94 142.79,93.14 C202.2 ; C201.1 144.49,93.78 v1(144.28,93.98)
  BOTTOM w0.381: v1(146.45,89.9) U15.L16 ; C301.1 134.61,79.65 134.47,79.79 v1(133.55,79.79) ; v1(168.05,89.55) 167.92,89.42 C207.1 ; v1(161.45,89.9) 162,89.34 C208.1 ; L23.2 v1(142.8,85.4) ; C279.1 v1(152.57,80.26) ; v1(161.45,85.9) U15.AE13 ; v1(142.67,91.37) 142.64,91.4 L19.2 ; C252.1 v1(148.7,82.62) ; v1(150.45,78.9) C281.1 ; C190.1 v1(152.7,95.25) ; v1(161.45,86.9) U15.AE14 ; C282.1 v1(148.7,80.97) ; C261.1 v1(142.8,81.48) ; v1(152.45,98.9) C165.1 ; U15.Y15 v1(156.45,87.9) ; R141.1 172.17,44.45 v1(172.1,44.52) ; C303.1 v1(144.58,72.32) ; C212.1 v1(160.09,87.74) ; C291.1 v1(134.79,76.09) ; L15.2 v1(159.09,94.4) ; C148.1 v1(168.24,104.25)
  BOTTOM w0.635: 90.44,46.35 C758.1 ; C758.1 91.47,45.33 ; C758.1 91.47,47.38 ; R831.1 85.33,87 ; C759.1 91.47,51.83 ; C759.1 90.44,50.8 ; C759.1 91.47,49.77 ; C291.1 135.57,76.56 ; 144.1,73.03 C303.1 ; TP227.1 91.9,43.95 ; TP227.1 90.82,42.88 ; TP227.1 90.82,43.95
P1P15V: length 81.8
  TOP w0.305: U15.T11 150.84,83.3 150.05,83.3 v1(149.45,83.9) 148.84,83.3 148,83.3 147.45,83.85 v1(147.45,83.9) ; v1(150.93,95.5) 150.93,94.38 v1(150.45,93.9) ; v1(152.45,83.9) 152.45,83.8 153.08,83.17 153.72,83.17 v1(154.45,83.9) ; v1(155.45,93.9) 155.45,94.01 154.86,94.6 154.15,94.6 v1(153.45,93.9)
  TOP w0.381: U15.M11 v1(147.45,83.9) ; v1(145.88,68.85) 146.53,68.85 146.92,69.23 146.92,69.85 ; v1(167.61,55.71) 167.59,55.74 167.59,56.53 167.86,56.79 R65.2 ; U15.Y17 v1(156.45,90.9) ; U15.AF9 v1(162.45,81.9) ; R65.2 168.61,55.73 v1(168.59,55.71) ; R65.2 169.42,56.79 169.69,56.53 169.69,55.81 v1(169.6,55.71) ; 150.58,107.63 v1(151.61,107.63) ; 150.58,107.63 C34.1 ; 150.58,107.63 150.58,106.96 150.96,106.58 v1(151.61,106.58) ; 150.58,107.63 150.58,108.28 150.96,108.66 v1(151.61,108.66) ; U15.V11 v1(154.45,83.9) ; U15.N20 v1(148.45,93.9) ; U15.Y11 v1(156.45,83.9) ; v1(173.09,55.71) 173.09,56.36 172.71,56.75 172.08,56.75 ; v1(165.95,53.19) 165.96,53.19 R64.1 ; 172.08,56.75 v1(172.08,55.71) ; 172.08,56.75 171.41,56.75 171.11,56.44 v1(171.11,55.71) ; 172.08,56.75 R66.2 ; U15.AF25 v1(162.45,98.9) ; 146.92,69.85 146.92,70.52 146.61,70.83 v1(145.88,70.83) ; 146.92,69.85 v1(145.88,69.85) ; 146.92,69.85 C96.1 ; U15.Y14 v1(156.45,86.9) ; U15.Y19 v1(156.45,92.9) ; U15.L14 v1(146.45,86.9) ; U15.AF13 v1(162.45,85.9) ; U15.AF11 v1(162.45,83.9) ; U15.AF23 v1(162.45,96.9) ; U15.P11 v1(149.45,83.9) ; U15.T11 v1(152.45,83.9) ; U15.AF21 v1(162.45,94.9) ; U15.L20 v1(146.45,93.9) ; U15.U20 v1(153.45,93.9) ; U15.W20 v1(155.45,93.9) ; U15.AF7 v1(162.45,79.9) ; U15.Y13 v1(156.45,85.9) ; U15.R20 v1(150.45,93.9)
  BOTTOM w0.305: C161.2 v1(158.81,96.4) ; v1(142.91,72.09) 142.91,72.24 143.08,72.4 L505.2 ; C583.1 143.07,71.01 v1(143.56,71.51) ; v1(137.91,71.25) 138.32,70.84 C576.2 ; C249.1 151.97,83.38 v1(151.97,82.62)
  BOTTOM w0.381: C167.1 v1(150.93,95.5) ; L16.2 v1(158.09,90.4) ; L18.2 v1(144.24,91.4) 143.75,91.4 C203.1 ; v1(162.45,83.9) U15.AF11 ; C250.1 v1(151.97,82.62) ; L24.2 v1(159.95,85.11) ; U15.Y14 v1(156.45,86.9) ; L13.2 v1(159.09,95.4) ; v1(162.45,85.9) C209.1 ; v1(156.45,83.9) C243.1 ; v1(154.45,83.9) C246.1 ; U15.Y13 v1(156.45,85.9) ; C188.1 v1(155.45,93.9) ; v1(146.45,93.9) C199.1 ; v1(148.45,93.9) C195.1 ; C149.1 v1(165.35,105.21) ; C213.1 v1(158.5,89.42) ; v1(152.45,83.9) C249.1 ; C233.1 v1(162.45,79.9) ; v1(147.45,83.9) C256.1 ; v1(162.45,81.9) C235.1 ; v1(151.51,72.36) 151.55,72.33 C302.1 ; C154.1 v1(162.45,98.9) ; C223.1 v1(146.45,86.9) C222.1 ; C300.1 v1(160.54,72.32) ; v1(156.45,92.9) U15.Y19 ; v1(150.45,93.9) C193.1 ; v1(162.45,94.9) 162.45,94.9 C178.1 ; v1(153.45,93.9) C191.1 ; U15.Y17 v1(156.45,90.9) ; C156.1 v1(162.45,96.9) ; L22.2 v1(142.8,87.4) ; L21.2 v1(142.8,89.4) ; v1(149.45,83.9) C253.1 ; v1(140.63,72.24) 140.54,72.33 C304.1
  vias: v1(159.12,64.14) v1(159.12,63.12) v1(159.12,62.1) v1(159.12,61.09) v1(160.13,64.14) v1(160.13,63.12) v1(160.13,62.1) v1(160.13,61.09) v1(161.15,64.14) v1(161.15,63.12) v1(161.15,62.1) v1(161.15,61.09) v1(162.17,64.14) v1(162.17,63.12) v1(162.17,62.1) v1(162.17,61.09) v1(163.18,64.14) v1(163.18,63.12) v1(163.18,62.1) v1(163.18,61.09) v1(164.2,67.18) v1(164.2,66.17) v1(164.2,65.15) v1(164.2,64.14) v1(164.2,63.12) v1(164.2,62.1) v1(164.2,61.09) v1(165.21,67.18) v1(165.21,66.17) v1(165.21,65.15) v1(165.21,64.14) v1(165.21,63.12) v1(165.21,62.1) v1(165.21,61.09)
P1P15V_DRAIN: length 2.1
  TOP w0.191: Q6.1 168.94,51 R76.1 R77.2
P1P15V_DRAIN_BUF: length 1.6
  TOP w0.191: R77.1 168.09,49.53 U33.4
P1P15V_EN: length 128.5
  TOP w0.191: U33.2 162.74,50.48 v1(162.73,50.47) 162.73,51.77 163.03,52.07 163.03,53.37 162.87,53.52 U32.12 ; v1(91.44,96.78) 91.37,96.85 U525.7 88.48,96.85 88.21,97.11 88.21,99.16 88.74,99.7 R832.2
  LY3 w0.122: v1(162.73,50.47) 162.73,51.4 161.21,52.92 144.27,52.92 138.57,47.21 106.61,47.21 v1(97.58,56.24)
  LY12 w0.122: v1(97.58,56.24) 90.55,63.28 90.55,95.89 v1(91.44,96.78)
P1P15V_FB: length 2.7
  TOP w0.191: R64.2 164.9,53.96 R62.1 163.84,53.95 163.39,53.95 162.91,54.43 U32.14
P1P15V_FET: length 12
  TOP w0.305: R65.1 168.29,53.37 Q6.3
  TOP w0.381: v1(171.06,54.78) 171.06,54.13 171.44,53.74 172.08,53.74 ; 172.08,53.74 172.76,53.74 173.14,54.13 v1(173.14,54.78) ; 172.08,53.74 v1(172.08,54.78) ; 172.08,53.74 R66.1 ; v1(168.59,54.78) 168.61,54.76 R65.1 ; v1(169.65,54.78) 169.59,54.72 169.59,53.83 169.46,53.7 R65.1 ; R65.1 167.7,53.7 167.56,53.83 167.56,54.77 v1(167.56,54.78)
P1P15V_MODE: length 2.6
  TOP w0.191: U32.15 163.74,54.87 R61.2 164.84,54.85 R63.1
P1P15V_PG: length 139.5
  TOP w0.191: R75.2 v1(161.63,51.8) 161.44,51.98 U32.9
  LY3 w0.122: v1(96.44,56.12) 96.44,54.47 103.91,47 106.45,47 106.5,46.95 139.06,46.95 144.75,52.64 160.27,52.64 161.11,51.8 v1(161.63,51.8)
  LY12 w0.122: v1(90.24,112.48) 90.24,107.78 89.6,107.14 89.6,94.97 89.59,94.96 89.59,94.57 89.6,94.56 89.6,62.96 v1(96.44,56.12)
  BOTTOM w0.191: U529.2 90.28,109.86 R839.2 90.49,112.23 v1(90.24,112.48)
P1P15V_SS: length 1.7
  TOP w0.191: v1(162.5,52.32) 162.39,52.43 U32.11
  BOTTOM w0.191: v1(162.5,52.32) 162.5,52.9 C317.1
P1P15V_SW: length 6.3
  TOP w0.191: U32.6 v1(160.09,51.75)
  BOTTOM w0.191: v1(160.09,51.75) 160.09,54.29 160.29,54.48 v1(160.29,57.18)
P1P15V_VCC: length 4.2
  TOP w0.191: C126.1 163.78,55.88 R61.1 163.77,55.93 163.54,56.16 161.7,56.16 161.44,55.9 U32.17
P1P21_DRAIN_EN: length 13.1
  TOP w0.191: v1(88.81,91.03) 88.73,91.11 86.95,91.11 U526.6
  BOTTOM w0.191: R197.1 87.25,95.05 87.43,95.23 88.72,95.23 89.73,94.22 91.27,94.22 91.66,93.82 91.66,93.13 91.16,92.62 90.72,92.62 90.32,92.21 90.32,91.4 U528.1 89.04,91.26 v1(88.81,91.03)
P1P21V: length 23.9
  TOP w0.381: U15.P20 v1(149.45,93.9) ; U15.N11 v1(148.45,83.9) ; v1(132.72,77.62) 132.72,78.65 ; 132.72,78.65 C91.1 ; 132.72,78.65 132.04,78.65 131.66,78.27 v1(131.66,77.62) ; 132.72,78.65 133.36,78.65 133.74,78.27 v1(133.74,77.62) ; U15.U11 v1(153.45,83.9) ; U15.L15 v1(146.45,87.9) ; U15.V20 v1(154.45,93.9) ; U15.Y16 v1(156.45,89.9)
  TOP w0.635: 86.76,55.99 TP229.1 ; TP229.1 87.83,55.99 ; TP229.1 87.83,54.92 ; TP229.1 86.76,54.92
  BOTTOM w0.381: v1(148.45,83.9) C254.1 ; C260.1 v1(143.12,84.34) ; C164.1 v1(154.44,96.97) ; v1(149.45,93.9) C194.1 ; C247.1 v1(153.28,82.11) ; C184.1 v1(157.73,94.82) ; v1(154.45,93.9) C189.1 ; v1(153.45,83.9) C248.1 ; U15.Y16 v1(156.45,89.9) ; v1(146.45,87.9) U15.L15
  BOTTOM w0.635: R837.1 96.52,88.59 v1(96.84,88.27) ; C762.1 87.22,55.53 TP229.1
P2.1: length 8.6
  TOP w0.191: TP64.1 14.92,121.56 15.72,120.76 15.72,119.77 15.97,119.52 15.97,118.17 17.69,116.45 U26.30
P2.2: length 7.3
  TOP w0.191: U26.31 17.4,115.96 15.57,117.79 15.57,119.13 14.92,119.78 TP66.1
P2.3: length 6
  TOP w0.191: U26.32 17.26,115.46 14.92,117.8 TP65.1
P2.4: length 4.9
  TOP w0.191: U26.33 17.1,114.96 15.97,116.09 15.68,116.09 TP67.1
P2.6: length 3.1
  TOP w0.191: U26.35 v1(20.87,113.95)
  BOTTOM w0.191: v1(20.87,113.95) 21.73,113.95 R608.2
P2.7: length 4.3
  TOP w0.191: U26.36 16.81,113.45 16.76,113.5 16.45,113.5 16.41,113.45 15.35,113.45 TP68.1
P2P5V: length 3
  TOP w0.635: TP231.1 87.45,64.47 ; TP231.1 86.38,64.47 ; TP231.1 87.45,65.54 ; TP231.1 86.38,65.54
  vias: v1(48.56,83.55) v1(48.56,82.66) v1(50.08,83.3) v1(50.72,82.53) v1(50.72,81.52) v1(86.66,75.93) v1(86.91,75.04) v1(87.55,76.06) v1(87.55,74.28) v1(87.93,75.17)
P3.2: length 7.7
  TOP w0.191: U26.39 14.74,111.96 14.25,112.45 14.25,114.26 TP112.1
P3.3: length 3.6
  TOP w0.191: U26.40 17.18,111.46 16.84,111.11 16.84,109.86 TP111.1
P3.4: length 5.4
  TOP w0.191: U26.41 20.97,108.84 19.37,107.24 TP113.1
P3.6: length 7.3
  TOP w0.191: U26.43 21.97,107.2 20.44,105.67 20.44,103.62 20.64,103.42 TP114.1
P3.7: length 5.2
  TOP w0.191: U26.44 22.47,106.93 21.28,105.75 21.28,104.78 TP115.1
P3P3_DRAIN_EN: length 4.7
  TOP w0.191: U526.7 v1(88.23,91.77) 90.01,91.77 U527.1
  BOTTOM w0.191: R196.1 86.8,91.77 v1(88.23,91.77)
P3P3V: length 324.4
  TOP w0.203: U559.3 17.08,97.93 C514.1
  TOP w0.254: U34.7 172.85,45.02 v1(172.49,45.38) ; U51.18 v1(130.7,29.68) ; U8.43 v1(140.99,120.08) ; U51.31 130.7,40.31 v1(130.77,40.38) ; U4.29 v1(141.03,145.18) ; U51.42 125.2,40.23 v1(125.23,40.26) ; J28.12 v1(183.41,7.41) ; J17.5 184.79,37.35 v1(184.84,37.4) ; v1(125.18,29.61) 125.2,29.63 U51.7 ; U4.43 v1(141.08,138.18) ; U8.29 v1(141.06,127.08)
  TOP w0.305: U46.16 11.58,29.47 C665.1 ; R549.2 v1(143.97,64.88)
  TOP w0.381: R543.2 v1(50.48,21.77) ; U15.AB25 v1(158.45,98.9) ; v1(78.84,11.09) 78.94,10.99 R200.2 ; R201.2 v1(49.85,11.28) ; U15.T20 v1(152.45,93.9) ; R843.2 v1(44.21,51.44) ; R542.2 v1(47.94,21.74) ; R79.2 v1(173.15,47.47) ; R10.2 v1(121.63,133.03) ; R39.2 v1(124.56,86.36) ; v1(175.61,26.73) 174.94,27.4 R526.2 ; C831.2 125.41,118.08 125.14,117.81 v1(125.14,117.53) ; U12.5 177.15,92.85 v1(177.14,92.86) ; VR2.3 v1(100.13,125.84) ; v1(152.23,70.83) 152.96,70.83 153.27,70.52 153.27,69.85 ; v1(133.67,57) 133.43,57.23 U43.24 ; R9.2 v1(121.68,134.62) ; U15.U6 v1(153.45,78.9) ; v1(184.48,87.17) 184.63,87.32 D6.2 ; U15.AC6 v1(159.45,78.9) ; J16.3 v1(112.7,34.84) ; R34.2 v1(160.34,109.37) ; R81.2 v1(150.29,39.08) ; 153.27,69.85 153.27,69.23 152.88,68.85 v1(152.23,68.85) ; 153.27,69.85 C97.1 ; 153.27,69.85 v1(152.23,69.85) ; U15.AA6 v1(157.45,78.9) ; U47.5 v1(143.74,58.73) ; J12.3 v1(112.7,41.84) ; U15.P25 v1(149.45,98.9) ; U15.R11 v1(150.45,83.9) ; U30.8 v1(103.82,54.27) ; VR1.3 v1(128.47,131.81) ; U15.L6 v1(146.45,78.9) ; U15.K25 v1(145.45,98.9) ; VR3.3 v1(135.56,108.7) ; U38.5 v1(70.49,16.34) ; v1(150.28,47.78) 150.29,47.76 R73.1 ; U15.W6 v1(155.45,78.9) ; J536.3 v1(167.95,37.63) ; v1(106.41,49.23) 106.36,49.19 U30.3 ; U15.AE24 v1(161.45,97.9) ; U49.24 v1(116.92,66.33) ; U15.AE12 v1(161.45,84.9) ; U15.V25 v1(154.45,98.9) ; v1(180.01,89.01) 180.77,89.78 C684.2 ; C700.2 v1(173.43,114.82) ; C664.2 v1(144.35,60.21) ; U55.5 v1(136.53,33.79) ; C670.1 v1(176.33,94.35) ; C665.1 v1(10.1,29.01) ; v1(144.44,105.28) 144.46,105.31 R20.2 ; U15.Y12 v1(156.45,84.9) ; U15.W11 v1(155.45,83.9) ; J21.2 v1(132.43,23.42) ; R51.1 v1(177.27,25.92) ; U15.M20 v1(147.45,93.9) ; U15.AE20 v1(161.45,93.9) ; U15.Y20 v1(156.45,93.9) ; R882.2 v1(129.65,108.48) ; U15.AE6 v1(161.45,78.9) ; U15.H25 v1(143.45,98.9) ; U15.Y25 v1(156.45,98.9) ; R717.2 v1(166.05,112.9) ; D15.2 v1(184.63,92.44) ; R22.2 v1(147,105.34) ; v1(177.05,88.45) 177.15,88.35 U16.5 ; U39.5 v1(76.84,16.34) ; R156.2 v1(116.41,77.64) ; R78.2 v1(171.65,47.46) ; U15.M25 v1(147.45,98.9) ; R52.1 v1(171.37,24.88) ; U15.AD25 v1(160.45,98.9) ; R716.2 v1(167.96,112.9) ; U15.AE8 v1(161.45,80.9) ; U15.N6 v1(148.45,78.9) ; R38.2 v1(124.56,87.63) ; C514.1 v1(17.07,97.02)
  TOP w0.635: 52.33,85.03 TP233.1 ; TP233.1 52.33,86.1 ; TP233.1 53.4,86.1 ; TP233.1 v1(52.86,84.18) R756.1 ; TP233.1 53.4,85.03 ; TP233.1 C765.2
  LY8_PLANE w0.635: 171.11,9.5 J113.1 ; J113.1 171.11,11.29 ; J113.1 172.9,9.5 ; J113.1 172.9,11.29 ; J112.1 10.98,6.21 ; J112.1 9.18,6.21 ; J112.1 9.18,4.42 ; J112.1 10.98,4.42 ; 38.86,94.43 J96.2 ; J96.2 40.51,96.07 ; J96.2 38.86,96.07 ; J96.2 40.51,94.43 ; 52.33,85.03 TP233.1 ; TP233.1 53.4,85.03 ; TP233.1 53.4,86.1 ; TP233.1 52.33,86.1 ; 89.19,140.31 J111.1 ; J111.1 89.19,142.1 ; J111.1 90.99,140.31 ; J111.1 90.99,142.1 ; J501.1 65.94,20.1 ; J501.1 64.24,21.81 ; J501.1 65.94,21.81 ; J501.1 64.24,20.1 ; 57.77,15.57 J45.1 57.77,17.45 ; 165.83,22.16 J105.3 ; J501.2 65.94,22.64 ; J501.2 64.24,24.35 ; J501.2 65.94,24.35 ; J501.2 64.24,22.64 ; 108.71,105.22 J74.3 ; J74.3 110.36,105.22 ; J74.3 108.71,106.87 ; J74.3 110.36,106.87 ; J43.1 119.52,12.88 ; J43.1 119.52,15.06 ; J43.1 117.33,12.88 ; J43.1 117.33,15.06 ; 123.95,14.79 J64.2 ; J64.2 125.6,14.79 ; J64.2 123.95,13.15 ; J64.2 125.6,13.15 ; 175.25,117.78 J506.1 175.25,115.9 ; 150.36,21.28 J23.3 ; 15.25,9.07 J104.3 ; 151.12,36.82 J22.1 151.12,34.94 ; 116.29,89.86 J73.2 ; 152.49,56.21 J503.2 ; 98.92,134.95 J103.3
  BOTTOM w0.203: v1(123.08,1.28) 123.26,1.45 U37.3 ; U36.3 v1(120.08,1.85) ; U37.7 v1(123.76,7.11) ; U36.7 v1(120.58,7.07)
  BOTTOM w0.305: C177.1 166.76,94.74 165.8,94.74 165.42,95.12 R256.2 ; v1(146.45,78.9) 145.74,79.61 L506.1 ; v1(157.45,78.9) 157.86,79.31 C242.1 ; v1(148.64,72.51) 148.61,72.48 148.14,72.48 147.19,71.52 C699.1
  BOTTOM w0.381: v1(18.12,52.7) 17.89,52.93 R783.2 ; R519.2 v1(69.29,17.26) ; C169.1 v1(147.45,98.9) ; R504.2 v1(83.82,17.26) ; U11.5 164.58,20.63 C654.2 v1(163.34,20.44) ; R765.2 v1(78.23,64.19) ; C206.1 v1(134.38,95.14) ; J23.3 150.36,23.22 150.5,23.36 C321.2 ; J104.3 17.53,9.07 C695.2 ; v1(155.45,83.9) C245.1 ; U539.8 135.74,108.88 v1(135.56,108.7) ; v1(116.92,66.33) 116.84,66.41 C675.2 ; C150.1 v1(159.59,105.64) ; R506.2 78.36,15.99 v1(78.73,16.36) ; C280.1 v1(153.45,78.9) 152.84,79.51 151.94,79.51 151.53,79.1 C557.2 ; R522.2 v1(66.67,17.26) ; R122.2 v1(180.02,84.2) ; C833.2 v1(101.28,123.83) ; R874.2 v1(126.05,131.88) ; v1(155.45,78.9) C278.1 ; R140.2 v1(110.17,39.09) ; v1(152.45,93.9) C192.1 ; R881.2 v1(126.02,111.12) ; R883.2 v1(132.32,107.31) ; R508.2 v1(71.83,17.26) ; C153.1 139.27,105.19 v1(139.38,105.31) ; U15.AE8 v1(161.45,80.9) ; v1(141.04,132.09) 141.1,132.09 141.21,132.19 R89.2 ; C298.2 v1(167.32,73.7) ; v1(103.75,89.37) 103.75,89.13 103.71,89.09 R258.2 ; C166.1 v1(152.68,97.47) ; C171.1 v1(145.45,98.9) ; R873.2 v1(137.48,139.06) ; U500.4 130.18,92.06 v1(129.55,91.44) ; R119.2 v1(172.68,84.77) ; v1(130.7,29.68) 130.49,29.89 C667.2 ; v1(125.18,29.61) 125.41,29.84 C666.2 ; v1(159.45,78.9) C276.1 ; R139.2 v1(111.44,39.09) ; v1(168.37,94.1) 168.29,94.18 C177.1 ; v1(179.62,96.88) 180.01,96.5 180.51,96.5 180.75,96.27 U502.1 ; v1(125.23,40.26) 125.41,40.08 C682.2 ; C137.1 141.3,138 141.11,138.18 v1(141.08,138.18) ; C158.1 v1(161.45,97.9) ; J111.1 90.06,141.21 89.25,140.39 87.89,140.39 C688.2 ; C136.1 141.89,145.18 v1(141.03,145.18) ; C168.1 v1(149.45,98.9) ; C689.2 v1(168.98,12.37) ; R209.2 v1(154.31,116.01) ; v1(148.45,78.9) C283.1 ; R875.2 v1(122.24,122) ; C185.1 v1(156.45,93.9) L17.2 ; v1(183.41,7.41) 183.08,7.09 C508.2 ; J73.2 116.29,92.37 C837.2 ; R143.2 v1(185.17,36.63) ; v1(147.07,108.08) 146.95,107.96 146.5,107.96 145.75,107.2 R21.2 ; R511.2 v1(125.93,72.22) ; J103.3 98.92,136.91 C687.2 ; C141.1 141.89,127.08 v1(141.06,127.08) ; v1(134.73,78.92) 134.75,78.94 C290.1 ; J45.1 56.72,16.62 C676.2 ; v1(161.45,84.9) C237.1 ; C196.1 v1(147.45,93.9) ; R505.2 v1(81.28,17.26) ; U538.8 125.07,117.6 v1(125.14,117.53) ; C176.1 135.25,98.08 v1(134.46,98.88) ; U15.AE6 v1(161.45,78.9) ; v1(178.33,96.53) 179.3,95.56 U502.4 ; C268.1 v1(134.57,85.93) ; C690.2 165.99,23.95 165.99,23.25 J105.3 ; v1(72.69,68.69) 72.18,68.18 R767.2 ; R151.2 v1(142.88,39.33) ; R763.2 v1(57.26,58.88) ; R86.1 v1(160.34,136.96) ; R257.2 111.44,89.33 111.19,89.58 v1(111.19,89.7) ; U500.1 v1(130.18,95.32) ; C517.1 v1(128.47,93.23) ; R647.1 v1(11.47,33.66) ; R879.2 104.14,119.5 v1(104.14,118.88) ; R128.2 v1(154.63,70.98) ; R877.2 92.67,118.54 v1(92.44,118.31) ; v1(156.45,84.9) U15.Y12 ; R94.1 v1(140.77,123.3) ; v1(161.45,93.9) U15.AE20 ; v1(154.45,98.9) C163.1 ; R528.1 v1(180.52,20.32) ; v1(158.45,98.9) U15.AB25 ; R869.2 v1(156.64,114.66) ; R147.2 v1(110.17,32.11) ; C299.2 v1(164.26,72.32) ; R804.2 v1(69.53,106.71) ; v1(149.08,105.7) 149.02,105.65 C151.2 ; R860.2 v1(96.32,66.28) ; v1(160.45,98.9) C157.1 ; R121.1 90.73,27.1 v1(90.62,27) ; L20.2 v1(144.24,90.4) ; R884.2 v1(166.69,34.62) ; R529.1 v1(171.13,20.46) ; R517.2 v1(74.4,15.99) ; R93.1 v1(144.39,124.57) ; C502.2 v1(133.67,57) ; R102.2 v1(141.02,114.1) ; v1(150.45,83.9) C251.1 ; v1(156.45,98.9) C162.1 ; v1(57.49,64.74) 58.51,64.74 R766.2 ; R125.1 v1(84.38,27.42) ; C696.2 v1(13.73,5.67) ; R520.1 v1(73.56,14.08) ; R84.1 v1(145.94,142.67) ; v1(140.99,120.08) 141.11,120.08 141.3,119.9 C147.1 ; C683.2 130.58,39.34 130.58,40.19 v1(130.77,40.38) ; U48.5 v1(98.65,66.99) ; U566.8 v1(99.72,123.82) ; R885.2 v1(165.42,34.7) ; R146.2 v1(111.44,32.11) ; C835.2 v1(140.54,109.02) ; v1(180.08,92.46) 180.49,92.06 180.49,91.52 180.09,91.13 U503.2 ; R142.2 v1(184.89,39.89) ; R764.2 v1(73.96,68.94) ; v1(157.45,78.9) C277.1 ; v1(159.68,118.39) 160.15,118.86 R98.1 ; R150.2 v1(144.15,39.33) ; R85.1 v1(160.27,140.22) ; U503.6 v1(174.98,90.48) ; L14.2 v1(143.45,98.9) C173.1 ; R878.2 v1(99.25,127.2) ; C285.1 v1(146.45,78.9) ; R835.1 v1(94.74,96.2) ; R92.1 v1(160.26,122.12)
  vias: v1(53.89,84.31) v1(54.28,86.47) v1(54.34,85.57)
